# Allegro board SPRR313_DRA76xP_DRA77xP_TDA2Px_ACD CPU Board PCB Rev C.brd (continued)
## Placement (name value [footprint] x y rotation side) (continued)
DS6  LED_GRN  [LED1206-59X59]  210.06 173.99 270 top
E1  0.47uF  [EMI-NFM21P]  31.11 155.57 270 top
E2  0.47uF  [EMI-NFM21P]  74.55 73.41 270 top
E3  0.47uF  [EMI-NFM21P]  74.55 68.96 270 top
E4  0.47uF  [EMI-NFM21P]  71.5 68.96 270 top
E5  0.47uF  [EMI-NFM21P]  71.5 73.41 270 top
E6  0.47uF  [EMI-NFM21P]  68.45 68.96 270 top
E7  0.47uF  [EMI-NFM21P]  121.16 58.39 180 top
E8  0.47uF  [EMI-NFM21P]  121.16 51.44 180 top
E9  0.47uF  [EMI-NFM21P]  121.16 55.22 180 top
E10  0.47uF  [EMI-NFM21P]  116.08 47.5 180 top
E11  0.47uF  [EMI-NFM21P]  163.7 45.72 90 top
E12  0.47uF  [EMI-NFM21P]  74.42 42.77 0 top
EXP_P1  QSE-020-01-L-D-A-K  [QSE_020]  62.1 87.2 270 bottom
EXP_P2  QSE-060-01-L-D-A-K  [QSE-060-0X-X-D-A]  92.58 112.6 0 bottom
EXP_P3  QSE-020-01-L-D-A-K  [QSE_020]  123.06 87.2 270 bottom
F1  8A_QuickBlow  [FUSEFOLDER-OMNI-BLOK]  190.25 164.72 90 top
FL1  DLW21SN121HQ2  [EMI-36X15-DLW21]  73.79 165.74 90 top
FL2  DLW21SN900HQ2  [EMI-36X15-DLW21-RDPADS]  151.64 164.59 90 top
FL3  DLW21SN900HQ2  [EMI-36X15-DLW21-RDPADS]  16.76 105.79 180 top
FL4  DLW21SN900HQ2  [EMI-36X15-DLW21-RDPADS]  18.8 102.74 180 top
FL5  DLW21SN900HQ2  [EMI-36X15-DLW21-RDPADS]  18.8 98.68 180 top
FL6  DLW21SN900HQ2  [EMI-36X15-DLW21-RDPADS]  16.76 95.63 180 top
FL7  DLW21SN121HQ2  [EMI-36X15-DLW21-RDPADS]  9.14 85.47 180 top
FL8  LW21SN900HQ2  [EMI-36X15-DLW21-RDPADS]  14.35 79.88 180 top
FL9  LW21SN900HQ2  [EMI-36X15-DLW21-RDPADS]  14.35 76.71 180 top
FL10  DLW21SN121HQ2  [EMI-36X15-DLW21]  17.14 123.95 180 bottom
FL11  DLW21SN121HQ2  [EMI-36X15-DLW21]  17.14 121.67 180 bottom
J1  NP  [JUMP1X2-6040]  4.7 22.35 0 top
J2  PJ-063BH  [PWRJACK-CUI-PJ063BH]  180.21 180.21 0 top
J3  USBMINI_AB  [SAMTEC-MUSB]  166.12 172.36 180 top
J4  NO-POP(2.54MM)  [JUMP1X2-6040]  15.75 163.58 180 top
J5  NO-POP(2.54MM)  [JUMP1X2-6040]  18.29 158.5 180 top
J6  NO-POP(2.54MM)  [JUMP1X2-6040]  15.75 153.42 180 top
J7  NP  [JUMP1X2-6040]  210.06 167.89 0 top
J8  MOLEX 052559-3679 ( mirror )  [CONN36-52559-MIRROR]  58.93 149.73 0 top
J9  NP-HEADER 3  [JUMP1X3-6040]  217.68 153.92 90 top
J10  NP-HEADER 3  [JUMP1X3-6040]  2.41 137.03 90 top
J11  99S20D-40MA5-Y-HSD-2  [CONN-RA-99S20D]  6.48 122.81 90 top
J12  SATA HEADER 7  [MOLEX-67491-002]  45.97 93.85 270 top
J13  MIPI-QSH-030  [QSH-030-01-F]  151.13 37.72 180 top
J14  PM5  [JUMP1X5-6040]  217.55 36.07 180 top
J15  MOLEX 052559-3679  [CONN36-52559-MIRROR]  41.25 31.5 180 top
J16  1757242  [CONN2-MSTBA]  37.21 18.92 180 top
J17  FH12A-40S-0.5SH(55)  [FH12-40-SH]  126.87 123.57 270 bottom
J18  AXT340124  [CONN-AXT40]  215.26 54.86 270 bottom
J19  QSH-030-01  [QSH-030-01-F]  171.13 27.65 0 bottom
J20  HEADER 5X2  [JUMP2X5-6040]  206.88 12.57 90 top
J21  HEADER 5X2  [JUMP2X5-6040]  196.72 20.83 90 top
JP1  NP-(HEADER 2  [JUMP1X2-6040]  193.29 32.51 0 top
JP2  NP-(HEADER 2  [JUMP1X2-6040]  207.77 32.51 0 top
L1  220Ohm  [L805-35X60]  36.2 164.59 270 top
L2  220Ohm  [L603-35X45]  169.8 168.91 0 top
L3  220Ohm  [L805-35X60]  20.57 166.62 180 top
L4  1K  [L603-35X45]  157.99 163.19 0 top
L5  220Ohm  [L603-35X45]  145.67 162.31 90 top
L6  220Ohm  [L603-35X45]  145.16 157.35 0 top
L7  220Ohm  [L603-35X45]  22.73 154.81 270 top
L8  220Ohm  [L603-35X45]  160.4 138.56 270 top
L9  220Ohm  [L603-35X45]  162.31 138.56 270 top
L10  2.2uH ( 7443330220)  [CHOKE-POWER-WE-HCC]  163.19 121.92 270 top
L11  8.2uH(744771008 )  [IND2-115X213-12MM]  188.59 120.65 270 top
L12  1uH  [IND2-65X90-IHLP1616]  163.07 79.38 270 top
L13  1uH  [IND2-65X90-IHLP1616]  154.18 72.52 0 top
L14  1uH  [IND2-65X90-IHLP1616]  173.1 72.77 180 top
L15  0.47uH  [IND2520-40X80]  136.02 65.28 270 top
L16  0.47uH  [IND2520-40X80]  139.19 65.28 270 top
L17  1uH  [IND2-65X90-IHLP1616]  154.18 67.69 0 top
L18  1uH  [IND2-65X90-IHLP1616]  166.24 60.45 90 top
L19  220Ohm  [L603-35X45]  50.8 51.31 0 top
L20  0.47uH  [IND2520-40X80]  135.89 54.86 90 top
L21  0.47uH  [IND2520-40X80]  139.19 54.86 90 top
L22  220Ohm  [L805-35X60]  170.18 50.42 270 top
L23  220Ohm  [L805-35X60]  185.42 38.23 270 top
L24  220Ohm  [L805-35X60]  181.99 35.69 270 top
L25  220Ohm  [L603-35X45]  28.32 130.81 90 bottom
L26  220Ohm  [L603-35X45]  20.19 127.38 180 bottom
L27  220Ohm  [L603-35X45]  36.58 124.46 0 bottom
L28  220Ohm  [L603-35X45]  36.58 122.68 0 bottom
L29  220Ohm  [L603-35X45]  36.58 121.03 0 bottom
L30  NP  [L805-35X60]  15.11 12.7 0 top
L31  0.47uH  [IND2520-40X80]  145.16 18.92 90 bottom
L32  220Ohm  [L603-35X45]  52.45 111.51 270 top
L33  220Ohm  [L603-35X45]  45.72 114.05 270 top
MHC1  MHC1  [MH62]  46.93 158.62 0 top
MHC2  MHC2  [MH62]  70.93 158.62 0 top
MHC3  MHC2  [MH93-125]  53.19 22.58 0 bottom
MHC4  MHC1  [MH93-125]  29.21 22.58 0 bottom
NOREF  -  []  220.85 0 90 top
NOREF#2  -  [unnamed#2]  5.08 185.29 0 top
NOREF#3  -  []  220.85 0 90 top
NOREF#4  -  [unnamed#2]  58.47 175.13 0 top
NOREF#5  -  []  -191.39 -215.57 0 top
NOREF#6  -  []  220.85 10.16 90 top
NOREF#7  -  [unnamed#2]  215.77 5.08 0 top
NOREF#8  -  [unnamed#2]  5.08 5.08 0 top
NOREF#9  -  []  0 190.37 0 top
NOREF#10  -  []  -191.39 -215.57 0 top
NOREF#11  -  [unnamed#2]  215.77 185.29 0 top
NOREF#12  -  []  65.02 120.9 0 top
NOREF#13  -  [unnamed#3]  156.72 30.99 0 bottom
NOREF#14  -  [unnamed#2]  5.08 5.08 180 bottom
NOREF#15  -  [unnamed#2]  5.08 185.29 180 bottom
NOREF#16  -  [unnamed#3]  187.2 30.99 0 bottom
NOREF#17  -  [unnamed#2]  215.77 5.08 180 bottom
NOREF#18  -  [unnamed#3]  202.44 13.84 0 bottom
NOREF#19  -  [unnamed#3]  208.15 60.83 0 bottom
NOREF#20  -  [unnamed#2]  215.77 185.29 180 bottom
P1  D4S20G-400A5-C  [CON_MB261]  150.37 174.96 0 top
P2  USB-A connector  [USB_A_SH]  77.34 169.42 180 top
P3  6605814-6  [AMP-6605814]  100.84 166.12 180 top
P4  6605814-6  [AMP-6605814]  121.92 166.12 180 top
P5  QSH-020-01-L-D-DP-A  [QSH-020-DP-A]  6.22 163.7 90 top
P6  PCIe 4X Connector  [PCIE_SMT_64]  34.38 139.19 90 top
P7  HDMI-RA-19-TYPEA  [HDMI-SMT-W-FLANGE-RDPADS]  8.5 102.74 270 top
P8  AU-Y1009_3-AB-R  [USB-AB-F-10PTH-RDPADS]  4.86 81.79 270 top
P9  MEC6-150-02-S-D-RA1  [MEC6-150-RA1]  7.49 52.58 180 top
P10  Mic In  [ST_3500]  156.08 17.53 180 top
P11  Line In  [ST_3500]  166.88 17.53 180 top
P12  Line Out  [ST_3500]  177.67 17.53 180 top
P13  Headphone Out  [ST_3500]  188.47 17.53 180 top
P14  Micro SD, Reverse  [MOLEX-502774-0891]  135.69 169.88 0 bottom
P15  QSH-020-01-L-D-DP-A  [QSH-020-DP-A#2]  41.05 32.28 180 bottom
Q1  SUD50P04-08  [TO-252-D-PAK]  192.79 146.81 180 top
Q2  CSD18501Q5A  [PWR-Q5A-SLPS319]  183.51 157.23 180 top
Q3  BSS138  [SOT23-28X44-GSD]  4.06 149.35 90 top
Q4  BSS138  [SOT23-28X44-GSD]  198.5 158.37 180 top
Q5  BSS138  [SOT23-28X44-GSD]  208.91 155.07 180 top
Q6  BSS138  [SOT23-28X44-GSD]  203.58 156.59 0 top
Q7  CSD18501Q5A  [PWR-Q5A-SLPS319]  168.91 133.35 0 top
Q8  CSD18501Q5A  [PWR-Q5A-SLPS319]  181.61 133.35 0 top
Q9  CSD18501Q5A  [PWR-Q5A-SLPS319]  171.45 129.79 180 top
Q10  CSD18501Q5A  [PWR-Q5A-SLPS319]  179.07 129.79 180 top
Q11  BSS138  [SOT23-28X44-GSD]  48.13 168.53 0 bottom
Q12  BSS138  [SOT23-28X44-GSD]  43.05 168.53 0 bottom
Q13  BSS138  [SOT23-28X44-GSD]  207.65 45.59 0 bottom
Q16  NX3008CBKS  [SOT363-16X45]  157.86 60.2 90 top
Q18  BSS138PS  [SOT363-16X45]  199.14 132.08 0 top
Q19  BSS138PS  [SOT363-16X45]  191.39 63.63 180 top
R1  100K  [R402-25]  36.2 161.42 270 top
R2  1K  [R402-25]  136.65 172.72 270 top
R3  10.7K  [R603-35X45]  84.96 169.42 180 top
R7  10K  [R402-25]  171.7 167.39 180 top
R8  100K  [R402-25]  18.03 166.62 270 top
R9  10K  [R402-25]  136.02 166.5 270 top
R10  NP  [R201-6P6SPC]  13.08 165.48 0 top
R11  NP  [R201-6P6SPC]  13.08 164.21 0 top
R12  10K  [R402-25]  52.7 163.96 270 top
R13  1K  [R402-25]  63.5 161.29 180 top
R14  NP  [R201-6P6SPC]  13.08 160.4 0 top
R15  4.99K  [R603-35X45]  82.3 160.15 180 top
R16  10K  [R402-25]  63.5 160.02 180 top
R17  NP  [R201-6P6SPC]  13.08 159.13 0 top
R18  1K  [R402-25]  63.5 157.48 180 top
R19  1.5K  [R402-25]  63.5 156.21 180 top
R20  10.7K  [R603-35X45]  78.49 156.21 90 top
R21  61.9K  [R603-35X45]  204.34 170.05 180 top
R22  NP  [R201-6P6SPC]  13.08 155.32 0 top
R23  4.7K  [R402-25]  192.79 156.08 0 top
R24  0  [R201-6P6SPC]  102.11 154.18 0 top
R25  NP  [R201-6P6SPC]  13.08 154.05 0 top
R26  NP  [R402-25]  24.64 154.05 90 top
R27  10K  [R402-25]  25.65 154.05 270 top
R28  10K  [R402-25]  26.67 154.05 270 top
R29  0  [R402-25]  27.69 154.05 90 top
R30  10K  [R402-25]  145.03 153.92 0 top
R31  61.9K  [R603-35X45]  204.34 165.74 180 top
R32  0.01  [R0508]  187.07 143.51 180 top
R33  2K  [R402-25]  97.66 151 0 top
R34  0  [R402-25]  119.38 150.24 270 top
R35  10K  [R402-25]  120.4 150.24 90 top
R36  1.5K  [R402-25]  198.5 154.81 270 top
R37  NP  [R402-25]  83.06 149.22 180 top
R38  NP  [R402-25]  86.23 149.22 0 top
R39  84.5K  [R603-35X45]  204.34 167.89 0 top
R40  NP  [R402-25]  83.06 148.21 180 top
R41  NP  [R402-25]  86.23 148.21 180 top
R42  10K  [R402-25]  146.3 147.96 0 top
R43  NP  [R402-25]  83.06 147.19 180 top
R44  NP  [R402-25]  86.23 147.19 180 top
R45  10K  [R402-25]  2.54 147.07 0 top
R46  1K  [R402-25]  203.07 159.13 0 top
R47  10K  [R402-25]  212.47 155.96 90 top
R48  0  [R402-25]  19.56 145.92 0 top
R49  NP  [R402-25]  87.5 145.92 90 top
R50  4.7K  [R402-25]  2.54 145.8 180 top
R51  10K  [R402-25]  4.95 145.8 0 top
R52  10K  [R402-25]  118.11 145.67 180 top
R53  4.99K  [R603-35X45]  79.25 143.76 270 top
R54  22  [R402-25]  54.1 145.54 90 top
R55  22  [R402-25]  55.12 145.54 90 top
R56  22  [R402-25]  63.5 145.29 90 top
R57  100  [R402-25]  37.21 145.16 180 top
R58  10K  [R402-25]  14.99 144.53 180 top
R59  820  [R402-25]  155.45 144.4 180 top
R60  10K  [R402-25]  211.2 153.54 90 top
R61  4.7K  [R402-25]  212.47 153.54 270 top
R62  4.7K  [R402-25]  14.99 143.38 180 top
R63  1K  [R402-25]  155.45 143.26 0 top
R64  NP  [R402-25]  87.5 142.75 90 top
R65  1.87K  [R603-35X45]  15.24 141.99 180 top
R66  10K  [R201-6P6SPC]  202.95 154.05 0 top
R67  4.7K  [R402-25]  159 141.22 180 top
R68  4.7K  [R402-25]  14.99 140.59 180 top
R69  NP  [R402-25]  106.81 135 180 top
R70  1K  [R201-6P6SPC]  117.98 135 270 top
R71  1K  [R201-6P6SPC]  119.25 135 270 top
R72  1K  [R201-6P6SPC]  120.52 135 270 top
R73  1K  [R201-6P6SPC]  121.79 135 270 top
R74  1K  [R201-6P6SPC]  123.06 135 270 top
R75  1K  [R201-6P6SPC]  124.33 135 270 top
R76  1K  [R201-6P6SPC]  125.6 135 270 top
R77  1K  [R201-6P6SPC]  126.87 135 270 top
R78  1K  [R201-6P6SPC]  130.18 135 270 top
R79  1K  [R201-6P6SPC]  131.44 135 270 top
R80  1K  [R201-6P6SPC]  132.72 135 270 top
R81  1K  [R201-6P6SPC]  133.99 135 270 top
R82  1K  [R201-6P6SPC]  135.25 135 270 top
R83  1K  [R201-6P6SPC]  136.53 135 270 top
R84  1K  [R201-6P6SPC]  137.79 135 270 top
R85  1K  [R201-6P6SPC]  139.06 135 270 top
R86  1.5K  [R402-25]  106.81 133.86 180 top
R87  10  [R603-35X45]  162.56 133.35 0 top
R88  10  [R603-35X45]  189.87 133.35 180 top
R89  0  [R402-25]  40.26 132.08 90 top
R90  0  [R402-25]  41.27 132.08 90 top
R91  0  [R201-6P6SPC]  106.68 131.95 270 bottom
R92  47K  [R402-25]  33.02 132.08 0 top
R93  0  [R402-25]  45.21 132.08 90 top
R94  0  [R402-25]  46.23 132.08 90 top
R95  4.7K  [R402-25]  211.71 141.1 90 top
R96  4.7K  [R402-25]  214.5 141.1 90 top
R97  10K  [R402-25]  215.77 141.1 90 top
R98  1.87K  [R603-35X45]  213.11 140.84 90 top
R99  49.9  [R402-25]  33.02 131.06 0 top
R100  2K  [R402-25]  104.01 130.68 0 top
R101  1K  [R402-25]  29.08 130.56 90 top
R102  47K  [R402-25]  33.02 130.05 0 top
R103  NP  [R402-25]  89.41 129.41 180 top
R104  NP  [R402-25]  92.58 128.91 0 top
R105  NP  [R402-25]  89.41 128.4 180 top
R106  NP  [R402-25]  92.58 127.89 180 top
R107  100  [R402-25]  62.87 132.08 180 top
R108  NP  [R402-25]  89.41 127.38 180 top
R109  NP  [R402-25]  92.58 126.87 180 top
R110  10K  [R402-25]  23.88 126.75 0 top
R111  49.9  [R402-25]  23.88 125.73 0 top
R112  NP  [R402-25]  93.85 125.6 90 top
R113  10K  [R201-6P6SPC]  117.98 123.55 270 top
R114  10K  [R201-6P6SPC]  119.25 123.55 270 top
R115  10K  [R201-6P6SPC]  120.52 123.55 270 top
R116  10K  [R201-6P6SPC]  121.79 123.55 270 top
R117  10K  [R201-6P6SPC]  123.06 123.55 270 top
R118  10K  [R201-6P6SPC]  124.33 123.55 270 top
R119  10K  [R201-6P6SPC]  125.6 123.55 270 top
R120  10K  [R201-6P6SPC]  126.87 123.55 270 top
R121  10K  [R201-6P6SPC]  130.18 123.55 270 top
R122  10K  [R201-6P6SPC]  131.44 123.55 270 top
R123  10K  [R201-6P6SPC]  132.72 123.55 270 top
R124  10K  [R201-6P6SPC]  133.99 123.55 270 top
R125  10K  [R201-6P6SPC]  135.25 123.55 270 top
R126  10K  [R201-6P6SPC]  136.53 123.55 270 top
R127  10K  [R201-6P6SPC]  137.79 123.55 270 top
R128  10K  [R201-6P6SPC]  139.06 123.55 270 top
R129  NP  [R402-25]  93.85 122.43 90 top
R130  10K  [R402-25]  103.12 117.22 270 top
R131  0  [R402-25]  101.47 116.71 180 top
R132  4.7K  [R402-25]  23.75 116.08 90 top
R133  0  [R402-25]  116.08 114.68 0 top
R134  10K  [R201-6P6SPC]  210.44 83.31 180 bottom
R135  0  [R402-25]  115.44 112.52 90 top
R136  10K  [R402-25]  116.46 112.52 270 top
R137  10K  [R201-6P6SPC]  210.44 82.04 180 bottom
R138  0.005  [R2725-125X250]  164.85 111.12 90 top
R139  10K  [R201-6P6SPC]  210.44 79.5 180 bottom
R140  4.99K  [R603-35X45]  31.5 106.43 0 top
R141  0.015  [R2512]  184.15 108.84 90 top
R142  10.7K  [R603-35X45]  31.24 96.14 0 top
R143  0  [R201-6P6SPC]  132.08 107.82 0 top
R144  0  [R402-25]  101.47 107.7 0 top
R145  10  [R402-25]  99.31 105.41 180 top
R146  10  [R402-25]  101.47 105.41 180 top
R147  10K  [R201-6P6SPC]  210.44 74.42 180 bottom
R148  49.9K  [R603-35X45]  163.96 104.14 180 top
R149  16K  [R402-25]  167.51 104.14 180 top
R150  0  [R402-25]  172.34 104.14 90 top
R151  0  [R402-25]  111.76 104.01 0 top
R152  10K  [R402-25]  113.41 103.76 90 top
R153  10K  [R201-6P6SPC]  210.44 73.15 180 bottom
R154  49.9  [R402-25]  163.7 102.23 0 top
R155  16K  [R402-25]  178.31 102.23 0 top
R156  84.5K  [R603-35X45]  181.86 102.23 0 top
R157  NP  [R201-6P6SPC]  110.36 49.28 180 bottom
R158  NP  [R201-6P6SPC]  110.36 48.39 180 bottom
R159  49.9  [R402-25]  181.86 100.33 180 top
R160  0.01  [R0508]  164.34 98.3 270 top
R161  10K  [R201-6P6SPC]  161.8 95.25 0 top
R162  0.01  [R0508]  182.12 93.85 90 top
R163  2.2K  [R402-25]  161.8 94.36 0 top
R164  0  [R201-6P6SPC]  98.17 91.69 90 top
R165  100  [R402-25]  78.05 78.36 180 top
R166  100  [R402-25]  81.61 78.36 180 top
R167  100  [R402-25]  79.83 77.47 180 top
R168  2.2K  [R402-25]  161.93 92.33 0 top
R169  NP  [R402-25]  86.49 88.9 270 top
R170  0  [R402-25]  87.76 88.9 270 top
R171  0  [R402-25]  96.27 88.39 270 top
R172  NP  [R402-25]  91.44 88.39 270 top
R173  0  [R402-25]  92.71 88.39 270 top
R174  NP  [R402-25]  97.66 88.52 270 top
R175  0  [R402-25]  98.93 88.52 270 top
R176  0  [R201-6P6SPC]  100.71 77.98 270 top
R177  0  [R201-6P6SPC]  102.49 77.98 270 top
R178  0  [R201-6P6SPC]  101.6 77.98 270 top
R179  0.01  [R0508]  163.83 83.95 0 top
R180  NP  [R402-25]  89.15 88.39 270 top
R181  0  [R402-25]  90.3 88.39 270 top
R182  0.01  [R0508]  159.26 84.33 0 top
R183  0.01  [R0508]  153.92 84.33 0 top
R184  NP  [R402-25]  93.85 88.39 270 top
R185  0  [R402-25]  95.12 88.39 270 top
R186  NP  [R402-25]  95.76 85.22 270 top
R187  0  [R402-25]  97.03 85.22 270 top
R188  NP  [R201-6P6SPC]  118.49 150.24 90 top
R189  0.01  [R0508]  176.91 81.79 0 top
R190  NP  [R402-25]  69.72 77.09 180 bottom
R191  0.01  [R0508]  137.54 71.12 0 top
R192  0.01  [R0508]  177.93 65.53 270 top
R193  0  [R201-6P6SPC]  13.59 70.99 90 top
R194  0.02  [R603-35X45]  180.72 73.79 0 top
R195  22  [R201-6P6SPC]  113.41 66.29 180 top
R196  0.01  [R0508]  177.93 69.22 270 top
R197  22  [R201-6P6SPC]  118.24 66.17 180 top
R198  22  [R201-6P6SPC]  118.24 60.2 180 top
R199  22  [R201-6P6SPC]  118.24 68.07 180 top
R200  22  [R201-6P6SPC]  118.24 68.96 180 top
R201  22  [R201-6P6SPC]  118.24 65.28 180 top
R202  22  [R201-6P6SPC]  118.24 67.18 180 top
R203  22  [R201-6P6SPC]  113.41 67.31 180 top
R204  0.01  [R0508]  176.66 61.85 270 top
R205  0.02  [R603-35X45]  144.65 63.75 0 top
R206  0  [R201-6P6SPC]  122.56 63.75 180 top
R207  22  [R201-6P6SPC]  113.41 64.39 180 top
R208  0.01  [R0508]  149.1 67.18 90 top
R209  0  [R201-6P6SPC]  124.84 58.8 180 top
R210  22  [R201-6P6SPC]  118.24 61.98 180 top
R211  100  [R402-25]  74.8 58.04 270 bottom
R212  22  [R201-6P6SPC]  113.41 65.28 180 top
R213  0  [R201-6P6SPC]  118.24 59.18 180 top
R214  0  [R201-6P6SPC]  124.84 59.31 0 bottom
R215  28K  [R402-25]  133.1 60.83 180 top
R216  0  [R201-6P6SPC]  124.84 56.26 180 top
R217  NP  [R402-25]  21.08 58.55 90 top
R218  0  [R201-6P6SPC]  124.84 57.91 180 top
R219  0.01  [R0508]  162.69 56.01 180 top
R220  0.01  [R0508]  182.12 54.48 270 top
R221  0  [R201-6P6SPC]  124.84 54.86 180 top
R222  10K  [R402-25]  19.56 56.26 270 top
R223  10  [R201-6P6SPC]  155.45 54.86 180 top
R224  0  [R201-6P6SPC]  124.84 57.02 0 top
R225  0.02  [R603-35X45]  144.91 56.64 0 top
R226  10  [R201-6P6SPC]  119.25 73.28 0 top
R227  2.2K  [R402-25]  158.37 54.48 180 top
R228  0  [R201-6P6SPC]  124.84 53.09 0 top
R229  10  [R201-6P6SPC]  155.45 53.34 180 top
R230  10  [R201-6P6SPC]  119.25 72.26 0 top
R231  0  [R201-6P6SPC]  124.84 54.1 180 top
R232  2.2K  [R402-25]  158.37 52.58 180 top
R233  0  [R201-6P6SPC]  67.69 56.77 180 bottom
R234  0  [R201-6P6SPC]  64.52 53.72 180 bottom
R235  0  [R201-6P6SPC]  117.6 45.09 180 top
R236  NP  [R402-25]  175.77 49.66 270 top
R237  10  [R402-25]  177.04 49.66 270 top
R238  10  [R402-25]  178.31 49.66 270 top
R239  10  [R402-25]  179.58 49.66 270 top
R240  10  [R402-25]  180.85 49.66 270 top
R241  22  [R402-25]  182.12 49.66 270 top
R242  10K  [R201-6P6SPC]  41.91 42.42 180 top
R243  0  [R201-6P6SPC]  61.09 49.02 180 bottom
R244  0  [R201-6P6SPC]  20.19 48.9 90 top
R245  0  [R201-6P6SPC]  112.39 45.59 180 top
R246  NP  [R402-25]  166.75 48.26 180 top
R247  0  [R201-6P6SPC]  62.23 47.75 180 bottom
R248  10K  [R201-6P6SPC]  158.62 48.26 0 top
R249  0.01  [R0508]  137.54 49.02 180 top
R250  10K  [R201-6P6SPC]  155.07 57.28 0 top
R251  2K  [R402-25]  166.75 47.12 180 top
R252  0  [R201-6P6SPC]  112.52 43.43 0 top
R253  NP  [R201-6P6SPC]  41.91 40.89 180 top
R254  NP  [R402-25]  166.75 45.97 180 top
R255  0  [R201-6P6SPC]  117.6 44.07 180 top
R256  NP  [R402-25]  166.75 44.83 180 top
R257  NP  [R201-6P6SPC]  41.91 44.32 0 top
R259  10K  [R201-6P6SPC]  41.91 43.31 180 top
R263  10K  [R201-6P6SPC]  195.07 40.89 0 top
R264  10K  [R201-6P6SPC]  206.5 40.26 180 top
R265  22  [R201-6P6SPC]  118.62 41.53 270 top
R266  NP  [R201-6P6SPC]  121.16 49.78 0 top
R267  2K  [R402-25]  121.16 46.35 0 top
R268  0  [R201-6P6SPC]  195.07 38.86 180 top
R269  10K  [R201-6P6SPC]  121.16 49.02 180 top
R270  0  [R201-6P6SPC]  206.76 38.35 0 top
R271  0  [R201-6P6SPC]  195.07 36.96 180 top
R272  22  [R201-6P6SPC]  119.13 38.23 180 top
R273  0  [R402-25]  13.84 34.92 90 top
R274  17.4K  [R603-35X45]  2.54 32.13 0 top
R275  100  [R402-25]  183.51 30.61 270 top
R276  36  [R402-25]  137.92 27.3 0 top
R277  NP-1K  [R402-25]  141.99 28.7 180 top
R278  36  [R402-25]  137.92 26.29 0 top
R279  20K  [R402-25]  184.02 25.91 0 top
R280  NP-1K  [R402-25]  141.99 27.56 180 top
R281  10K  [R402-25]  141.99 30.99 0 top
R282  0  [R402-25]  141.99 29.84 0 top
R283  100K  [R402-25]  152.91 27.18 0 bottom
R284  NP-10K  [R402-25]  138.81 29.46 180 top
R285  0  [R402-25]  138.81 30.61 0 top
R286  28K  [R402-25]  152.91 24.13 0 bottom
R287  62  [R1206-40X70]  201.17 18.29 180 bottom
R288  62  [R1206-40X70]  201.17 25.91 0 bottom
R289  62  [R1206-40X70]  211.2 19.3 180 top
R290  62  [R1206-40X70]  216.28 19.3 180 top
R291  28K  [R402-25]  152.91 22.1 0 bottom
R292  0  [R402-25]  60.07 15.75 180 top
R296  NP  [R402-25]  60.07 14.73 180 top
R297  1K  [R402-25]  213.74 172.72 90 bottom
R298  10K  [R402-25]  16.76 176.78 90 bottom
R299  220  [R402-25]  121.79 175.77 180 bottom
R300  220  [R402-25]  113.54 175.77 0 bottom
R301  220  [R402-25]  100.84 175.77 180 bottom
R302  220  [R402-25]  91.95 175.77 0 bottom
R305  NP  [R402-25]  70.99 177.16 0 bottom
R306  10K  [R402-25]  70.99 176.02 180 bottom
R307  0  [R402-25]  44.2 174.37 180 bottom
R308  10K  [R402-25]  36.58 174.37 0 bottom
R309  10K  [R402-25]  27.3 160.91 180 bottom
R310  NP  [R402-25]  76.2 176.15 180 bottom
R311  10K  [R402-25]  76.2 175.01 0 bottom
R312  680K  [R402-25]  47.62 172.47 180 bottom
R313  680K  [R402-25]  42.55 172.47 180 bottom
R314  330K  [R402-25]  47.62 171.32 0 bottom
R315  330K  [R402-25]  42.55 171.32 0 bottom
R316  0  [R201-6P6SPC]  8.51 165.48 180 bottom
R317  10K  [R402-25]  56.01 163.7 90 bottom
R318  10K  [R402-25]  149.48 162.81 270 bottom
R319  10K  [R402-25]  59.18 162.56 90 bottom
R320  47K  [R402-25]  47.62 165.99 0 bottom
R321  47K  [R402-25]  42.55 165.99 0 bottom
R322  0  [R402-25]  4.06 161.93 90 bottom
R323  NP  [R402-25]  126.11 160.66 180 bottom
R324  1.87K  [R603-35X45]  82.3 160.27 0 bottom
R325  NP  [R402-25]  147.07 160.02 0 bottom
R326  40.2K  [R402-25]  147.07 158.88 180 bottom
R327  11K  [R402-25]  99.57 157.48 90 bottom
R328  10K  [R402-25]  56.01 157.35 270 bottom
R329  NP  [R201-6P6SPC]  168.78 157.23 90 bottom
R330  47K  [R402-25]  140.84 156.72 90 bottom
R331  47K  [R402-25]  137.29 156.72 270 bottom
R332  NP  [R402-25]  136.27 156.72 90 bottom
R333  47K  [R402-25]  132.72 156.72 270 bottom
R334  47K  [R402-25]  131.7 156.72 90 bottom
R335  47K  [R402-25]  128.14 156.72 270 bottom
R336  NP  [R402-25]  155.19 156.21 0 bottom
R337  40.2K  [R402-25]  155.19 155.07 180 bottom
R338  NP  [R402-25]  99.57 154.69 270 bottom
R339  33  [R402-25]  128.91 154.05 0 bottom
R340  NP  [R402-25]  27.69 154.05 90 bottom
R341  1K  [R402-25]  121.28 153.67 90 bottom
R342  0  [R603-35X45]  119.25 153.67 90 bottom
R343  33  [R402-25]  139.57 153.54 90 bottom
R344  33  [R402-25]  138.56 153.54 90 bottom
R345  33  [R402-25]  135 153.54 90 bottom
R346  33  [R402-25]  133.99 153.54 90 bottom
R347  33  [R402-25]  130.43 153.54 90 bottom
R348  2K  [R402-25]  83.06 153.54 0 bottom
R349  10K  [R402-25]  26.67 153.03 90 bottom
R350  1K  [R402-25]  199.52 176.91 90 bottom
R351  NP  [R402-25]  83.06 152.15 180 bottom
R352  22  [R402-25]  55.63 151.13 90 bottom
R353  NP  [R402-25]  83.06 151.13 180 bottom
R354  10K  [R402-25]  66.67 151.13 270 bottom
R355  22  [R402-25]  63.63 151.13 90 bottom
R356  5.6K  [R402-25]  83.06 149.1 180 bottom
R357  2.49K  [R402-25]  83.06 148.08 180 bottom
R358  10K  [R402-25]  146.3 147.96 0 bottom
R359  10K  [R201-6P6SPC]  117.6 146.43 0 bottom
R360  10K  [R201-6P6SPC]  117.6 145.67 0 bottom
R361  10.7K  [R603-35X45]  77.47 145.54 0 bottom
R362  10K  [R402-25]  114.55 145.16 0 bottom
R363  NP  [R402-25]  117.09 144.65 180 bottom
R364  10K  [R402-25]  114.55 144.15 0 bottom
R365  10K  [R402-25]  62.61 144.02 270 bottom
R366  10K  [R201-6P6SPC]  117.35 143.64 0 bottom
R367  5.6K  [R402-25]  91.11 143.18 180 bottom
R368  NP  [R402-25]  88.82 143.18 180 bottom
R369  10K  [R402-25]  29.72 142.88 90 bottom
R370  10K  [R402-25]  27.81 142.88 90 bottom
R371  10K  [R402-25]  117.09 142.62 180 bottom
R372  10K  [R402-25]  26.29 142.11 180 bottom
R373  2.49K  [R402-25]  91.11 142.03 0 bottom
R374  NP  [R402-25]  88.82 142.03 0 bottom
R375  10K  [R201-6P6SPC]  117.6 141.6 0 bottom
R376  10K  [R201-6P6SPC]  117.6 140.84 0 bottom
R377  10K  [R402-25]  149.22 140.46 180 bottom
R378  NP  [R402-25]  146.05 139.7 0 bottom
R379  11K  [R402-25]  104.01 139.45 180 bottom
R380  10K  [R201-6P6SPC]  117.86 139.19 0 bottom
R381  NP  [R402-25]  38.35 137.54 0 bottom
R382  10K  [R201-6P6SPC]  146.05 138.56 180 bottom
R383  10K  [R201-6P6SPC]  117.86 138.43 0 bottom
R384  47K  [R402-25]  152.78 138.18 270 bottom
R385  47K  [R402-25]  151.76 138.18 270 bottom
R386  47K  [R402-25]  150.75 138.18 270 bottom
R387  47K  [R402-25]  149.73 138.18 270 bottom
R388  47K  [R402-25]  148.72 138.18 270 bottom
R389  47K  [R402-25]  147.7 138.18 270 bottom
R390  10K  [R201-6P6SPC]  117.86 137.67 0 bottom
R391  10K  [R201-6P6SPC]  146.05 137.54 180 bottom
R392  10K  [R201-6P6SPC]  117.86 136.91 0 bottom
R393  10K  [R201-6P6SPC]  146.05 136.53 180 bottom
R394  220  [R402-25]  82.04 135.89 180 bottom
R395  47K  [R402-25]  144.78 135.51 0 bottom
R396  10K  [R201-6P6SPC]  120.4 135.51 90 bottom
R397  10K  [R201-6P6SPC]  117.86 135.51 90 bottom
R398  47K  [R402-25]  144.78 134.37 0 bottom
R399  NP  [R402-25]  106.43 134.37 270 bottom
R400  NP  [R402-25]  75.56 133.22 0 bottom
R401  0  [R402-25]  184.02 133.1 0 bottom
R402  0  [R402-25]  169.29 133.1 180 bottom
R403  2K  [R402-25]  89.41 133.1 0 bottom
R404  10K  [R402-25]  30.23 133.1 180 bottom
R405  NP  [R402-25]  79.63 132.59 0 bottom
R406  10  [R201-6P6SPC]  32.89 132.08 180 bottom
R407  NP  [R402-25]  89.41 131.95 180 bottom
R408  10K  [R402-25]  79.25 131.19 180 bottom
R409  NP  [R402-25]  89.41 130.94 180 bottom
R410  40.2K  [R402-25]  20.19 130.68 0 bottom
R411  10K  [R402-25]  67.06 130.18 180 bottom
R412  NP  [R402-25]  79.38 130.05 0 bottom
R413  10  [R201-6P6SPC]  32.89 130.05 180 bottom
R414  0  [R402-25]  177.55 129.79 0 bottom
R415  47K  [R402-25]  148.21 129.67 90 bottom
R416  47K  [R402-25]  147.07 129.67 270 bottom
R417  0  [R402-25]  169.54 129.29 270 bottom
R418  0  [R402-25]  150.62 129.29 90 bottom
R419  10K  [R402-25]  79.25 128.91 180 bottom
R420  NP  [R402-25]  152.27 128.78 180 bottom
R421  5.6K  [R402-25]  89.41 128.78 180 bottom
R422  NP  [R402-25]  67.06 128.91 0 bottom
R423  NP  [R402-25]  20.19 128.65 180 bottom
R424  2.49K  [R402-25]  89.41 127.76 180 bottom
R425  10K  [R402-25]  60.33 126.62 90 bottom
R426  10K  [R402-25]  59.69 131.57 0 bottom
R427  10K  [R402-25]  62.61 125.09 180 bottom
R428  10K  [R402-25]  62.48 129.54 180 bottom
R429  10K  [R402-25]  208.41 133.73 90 bottom
R430  2K  [R402-25]  97.33 122.73 180 bottom
R431  NP  [R402-25]  95.05 122.73 180 bottom
R432  NP  [R402-25]  97.33 121.71 0 bottom
R433  NP  [R402-25]  95.05 121.71 0 bottom
R434  0  [R201-6P6SPC]  131.83 121.28 270 bottom
R435  1K  [R201-6P6SPC]  123.7 121.16 270 bottom
R436  1K  [R201-6P6SPC]  123.06 121.16 270 bottom
R437  1K  [R201-6P6SPC]  122.43 121.16 270 bottom
R438  1K  [R201-6P6SPC]  121.79 121.16 270 bottom
R439  1K  [R201-6P6SPC]  121.16 121.16 270 bottom
R440  1K  [R201-6P6SPC]  120.52 121.16 270 bottom
R441  1.5K  [R402-25]  172.09 120.78 0 bottom
R442  40.2K  [R402-25]  17.02 119.89 180 bottom
R443  1K  [R201-6P6SPC]  214 128.91 270 bottom
R444  1K  [R201-6P6SPC]  216.79 128.52 0 bottom
R445  NP  [R402-25]  177.8 118.11 90 bottom
R446  0  [R402-25]  176.66 118.11 270 bottom
R447  NP  [R402-25]  17.02 117.86 0 bottom
R448  NP  [R402-25]  20.19 116.84 180 bottom
R449  10  [R201-6P6SPC]  25.53 116.2 90 bottom
R450  10  [R201-6P6SPC]  24.77 116.2 90 bottom
R451  4.7K  [R402-25]  26.42 116.08 270 bottom
R452  10K  [R201-6P6SPC]  146.81 115.7 0 bottom
R453  10K  [R402-25]  29.84 115.57 270 bottom
R454  27K  [R402-25]  32 115.44 270 bottom
R455  1K  [R201-6P6SPC]  218.06 84.58 0 bottom
R456  40.2K  [R402-25]  20.19 114.81 0 bottom
R457  0  [R201-6P6SPC]  125.35 115.44 0 bottom
R458  NP  [R201-6P6SPC]  125.35 114.68 0 bottom
R459  1K  [R201-6P6SPC]  218.06 83.31 0 bottom
R460  10K  [R201-6P6SPC]  128.52 113.54 0 bottom
R461  NP  [R402-25]  197.49 82.42 180 bottom
R462  1K  [R201-6P6SPC]  218.06 82.04 0 bottom
R463  10K  [R402-25]  197.49 81.15 0 bottom
R464  1K  [R201-6P6SPC]  218.06 80.77 0 bottom
R465  0  [R201-6P6SPC]  129.54 111.25 0 bottom
R466  1K  [R402-25]  13.08 110.74 270 bottom
R467  NP  [R402-25]  10.16 110.74 180 bottom
R468  10K  [R402-25]  197.49 79.88 0 bottom
R469  1K  [R201-6P6SPC]  218.06 79.5 0 bottom
R470  1K  [R402-25]  17.37 109.75 90 bottom
R471  NP  [R402-25]  203.33 79.25 180 bottom
R472  NP  [R402-25]  10.16 109.73 180 bottom
R473  1.87K  [R603-35X45]  31.5 106.3 180 bottom
R474  10K  [R201-6P6SPC]  210.44 78.23 180 bottom
R475  NP  [R402-25]  197.49 78.61 180 bottom
R476  20K  [R402-25]  184.15 108.84 180 bottom
R477  1K  [R201-6P6SPC]  218.06 78.23 0 bottom
R478  10K  [R402-25]  203.33 77.98 0 bottom
R479  0  [R402-25]  179.07 108.33 0 bottom
R480  15K  [R402-25]  168.15 107.95 90 bottom
R481  1K  [R201-6P6SPC]  218.06 76.96 0 bottom
R482  10K  [R201-6P6SPC]  210.44 76.96 180 bottom
R483  NP  [R201-6P6SPC]  8.13 106.93 180 bottom
R484  NP  [R201-6P6SPC]  5.84 106.93 180 bottom
R485  1K  [R201-6P6SPC]  218.06 75.69 0 bottom
R486  100  [R402-25]  203.45 75.06 0 bottom
R487  NP  [R201-6P6SPC]  8.89 105.54 180 bottom
R488  10K  [R402-25]  168.53 63.5 90 bottom
R489  10K  [R201-6P6SPC]  76.07 105.16 0 bottom
R490  1K  [R201-6P6SPC]  218.06 74.42 0 bottom
R491  NP  [R201-6P6SPC]  8.89 104.78 180 bottom
R492  NP  [R402-25]  172.21 104.14 270 bottom
R493  10K  [R201-6P6SPC]  68.45 104.01 0 bottom
R494  NP  [R201-6P6SPC]  8.89 104.01 180 bottom
R495  1K  [R201-6P6SPC]  218.06 73.15 0 bottom
R496  10K  [R402-25]  141.99 59.44 180 bottom
R497  0  [R402-25]  197.49 83.57 180 bottom
R498  0  [R402-25]  200.66 70.87 180 bottom
R499  NP  [R402-25]  197.74 70.87 180 bottom
R500  0  [R603-35X45]  150.88 101.09 180 bottom
R501  10K  [R201-6P6SPC]  119 100.33 0 bottom
R502  10K  [R402-25]  200.66 69.6 180 bottom
R503  10K  [R402-25]  197.74 69.6 0 bottom
R504  330  [R402-25]  216.48 69.52 270 bottom
R505  10K  [R402-25]  197.74 68.33 0 bottom
R506  10K  [R402-25]  203.58 67.69 180 bottom
R507  330  [R402-25]  216.48 67.49 270 bottom
R508  NP  [R402-25]  197.74 67.06 180 bottom
R509  NP  [R402-25]  203.58 66.42 0 bottom
R510  330  [R402-25]  216.48 65.46 270 bottom
R511  0  [R201-6P6SPC]  129.67 91.06 270 bottom
R512  10K  [R402-25]  203.58 65.02 180 bottom
R513  0.01  [R0508]  150.62 94.49 180 bottom
R514  0.01  [R0508]  145.8 94.49 180 bottom
R515  0  [R201-6P6SPC]  68.33 94.36 90 bottom
R516  10K  [R402-25]  203.58 63.75 180 bottom
R517  330  [R402-25]  216.48 63.42 270 bottom
R518  10K  [R402-25]  9.53 92.2 0 bottom
R519  0  [R402-25]  202.69 56.39 270 bottom
R520  0  [R201-6P6SPC]  98.3 91.69 90 bottom
R521  NP  [R402-25]  9.53 91.06 180 bottom
R522  10K  [R402-25]  9.53 89.92 0 bottom
R523  NP  [R402-25]  9.53 88.77 180 bottom
R524  0  [R201-6P6SPC]  70.87 91.19 270 bottom
R525  0  [R201-6P6SPC]  88.39 74.68 90 bottom
R526  0  [R201-6P6SPC]  69.85 91.19 270 bottom
R527  0  [R201-6P6SPC]  85.72 74.68 90 bottom
R528  10K  [R402-25]  67.94 86.49 180 bottom
R529  0  [R201-6P6SPC]  75.95 91.19 270 bottom
R530  0  [R201-6P6SPC]  73.79 91.19 270 bottom
R531  0  [R201-6P6SPC]  72.77 91.19 270 bottom
R532  0  [R201-6P6SPC]  71.75 91.19 270 bottom
R533  0.02  [R603-35X45]  171.83 81.79 90 top
R534  0  [R402-25]  191.77 51.05 270 bottom
R535  NP  [R402-25]  69.72 83.19 180 bottom
R536  0  [R402-25]  69.72 81.15 180 bottom
R537  0.02  [R603-35X45]  173.48 59.94 270 top
R538  10K  [R201-6P6SPC]  148.21 79.88 90 bottom
R539  0  [R402-25]  69.72 82.17 180 bottom
R540  NP  [R402-25]  69.72 80.14 180 bottom
R541  1.5K  [R402-25]  114.3 79.25 90 bottom
R542  0  [R402-25]  69.72 79.12 180 bottom
R543  0  [R402-25]  69.72 78.11 180 bottom
R544  NP  [R201-6P6SPC]  167.39 75.69 270 top
R545  0  [R201-6P6SPC]  166.5 75.69 90 top
R546  2K  [R402-25]  168.4 75.56 90 bottom
R547  1.74K  [R402-25]  170.05 75.06 180 bottom
R548  0.02  [R603-35X45]  180.72 77.6 0 top
R549  0.02  [R603-35X45]  152.53 58.67 180 top
R550  10K  [R402-25]  122.43 40.64 0 bottom
R551  47K  [R402-25]  122.43 42.42 0 bottom
R552  23.2K  [R402-25]  121.41 43.56 180 bottom
R553  22  [R201-6P6SPC]  122.56 62.48 180 bottom
R554  0  [R201-6P6SPC]  109.35 68.33 180 bottom
R555  22  [R201-6P6SPC]  124.84 60.58 180 top
R556  0  [R201-6P6SPC]  109.35 67.31 180 bottom
R557  22  [R201-6P6SPC]  118.24 64.9 180 bottom
R558  0  [R201-6P6SPC]  109.35 67.82 180 top
R559  22  [R201-6P6SPC]  113.41 68.2 180 top
R560  22  [R201-6P6SPC]  118.24 63.63 180 bottom
R561  22  [R201-6P6SPC]  118.24 65.79 180 bottom
R562  22  [R201-6P6SPC]  118.24 62.48 180 bottom
R563  22  [R201-6P6SPC]  122.56 64.52 180 bottom
R564  22  [R201-6P6SPC]  122.56 64.9 180 top
R565  22  [R201-6P6SPC]  118.24 62.87 180 top
R566  22  [R201-6P6SPC]  122.56 63.37 180 bottom
R567  22  [R201-6P6SPC]  118.24 61.59 180 bottom
R568  22  [R201-6P6SPC]  124.84 59.69 180 top
R569  10K  [R402-25]  12.7 23.5 0 top
R570  22  [R201-6P6SPC]  122.56 62.87 180 top
R571  0  [R201-6P6SPC]  115.7 70.36 180 top
R572  10K  [R402-25]  11.18 26.67 180 top
R573  NP  [R201-6P6SPC]  74.93 58.55 0 top
R574  0  [R201-6P6SPC]  118.24 60.71 180 bottom
R575  0.02  [R603-35X45]  177.67 58.67 0 top
R576  NP  [R201-6P6SPC]  74.93 57.66 0 top
R577  22  [R201-6P6SPC]  118.24 64.01 180 top
R578  0  [R201-6P6SPC]  124.84 56.52 180 bottom
R579  0  [R402-25]  15.37 59.18 90 bottom
R580  0  [R201-6P6SPC]  118.24 61.09 180 top
R581  22  [R402-25]  50.42 57.15 0 bottom
R582  0  [R201-6P6SPC]  124.84 57.53 180 bottom
R583  0  [R201-6P6SPC]  124.84 60.2 180 bottom
R584  22  [R402-25]  50.42 56.13 0 bottom
R585  10K  [R402-25]  21.08 57.28 90 bottom
R586  0  [R201-6P6SPC]  124.84 55.63 0 bottom
R587  10K  [R402-25]  8.51 56.64 270 bottom
R588  10K  [R402-25]  7.49 56.64 270 bottom
R589  10K  [R402-25]  6.48 56.64 270 bottom
R590  10K  [R402-25]  5.46 56.64 270 bottom
R591  10K  [R402-25]  4.45 56.64 270 bottom
R592  NP  [R402-25]  19.56 56.26 90 bottom
R593  22  [R402-25]  124.84 53.59 180 bottom
R594  0  [R402-25]  198.12 55.5 270 bottom
R595  NP  [R402-25]  196.85 55.5 270 bottom
R596  0  [R201-6P6SPC]  124.84 54.61 0 bottom
R597  10K  [R201-6P6SPC]  19.43 18.29 90 bottom
R598  22  [R402-25]  124.84 52.58 180 bottom
R599  22  [R402-25]  124.84 51.56 180 bottom
R600  10K  [R402-25]  203.58 51.18 270 bottom
R601  10K  [R402-25]  194.31 51.05 270 bottom
R602  NP  [R402-25]  193.04 51.05 270 bottom
R603  0  [R201-6P6SPC]  117.6 45.21 180 bottom
R604  20K  [R402-25]  180.72 49.66 90 bottom
R605  20K  [R402-25]  178.18 49.66 90 bottom
R606  2K  [R402-25]  175.9 49.66 90 bottom
R607  0  [R201-6P6SPC]  112.39 45.72 180 bottom
R608  10K  [R402-25]  207.65 49.15 0 bottom
R609  10K  [R402-25]  198.37 49.02 0 bottom
R610  2K  [R402-25]  166.75 48.26 0 bottom
R611  22  [R402-25]  121.16 45.85 180 bottom
R612  NP  [R402-25]  166.75 47.12 0 bottom
R613  NP  [R201-6P6SPC]  112.52 43.56 0 bottom
R614  NP  [R402-25]  166.75 45.97 0 bottom
R615  0  [R201-6P6SPC]  201.29 45.59 270 bottom
R616  0  [R402-25]  200.03 45.59 270 bottom
R617  NP  [R402-25]  166.75 44.83 0 bottom
R618  2.2K  [R402-25]  112.14 41.78 270 bottom
R619  20K  [R402-25]  4.32 44.32 90 bottom
R620  20K  [R402-25]  8.38 43.94 90 bottom
R621  20K  [R402-25]  7.37 43.94 90 bottom
R622  20K  [R402-25]  6.35 43.94 90 bottom
R623  20K  [R402-25]  5.33 43.94 90 bottom
R624  0  [R201-6P6SPC]  110.36 47.62 180 bottom
R625  10K  [R201-6P6SPC]  208.03 43.05 180 bottom
R626  2.2K  [R402-25]  112.65 39.62 90 bottom
R628  0  [R402-25]  166.5 41.66 0 bottom
R630  0  [R402-25]  110.62 41.78 90 bottom
R632  2.2K  [R402-25]  166.5 40.51 0 bottom
R633  330  [R402-25]  163.96 40.51 0 bottom
R634  NP  [R402-25]  8.51 40.39 0 bottom
R635  2.2K  [R402-25]  210.31 40.26 90 bottom
R636  2.2K  [R402-25]  209.17 40.26 90 bottom
R637  4.7K  [R402-25]  153.03 40.89 90 bottom
R638  4.7K  [R402-25]  154.05 40.89 90 bottom
R639  2K  [R402-25]  17.02 39.5 180 bottom
R640  0  [R402-25]  155.07 40.89 90 bottom
R641  NP  [R402-25]  111 39.62 90 bottom
R642  0.01  [R0508]  132.59 40.64 270 bottom
R643  10K  [R402-25]  115.7 39.5 180 bottom
R644  4.7k  [R402-25]  25.91 44.32 270 bottom
R645  NP  [R402-25]  166.5 38.23 0 bottom
R646  2K  [R402-25]  17.02 38.23 180 bottom
R647  10K  [R402-25]  205.61 84.96 180 bottom
R648  2.2K  [R402-25]  210.57 36.96 270 bottom
R649  2.2K  [R402-25]  209.3 36.96 270 bottom
R650  4.7k  [R402-25]  17.53 35.81 270 bottom
R651  4.7K  [R402-25]  157.48 40.89 90 bottom
R652  NP  [R402-25]  156.34 40.89 270 bottom
R653  0  [R1206-40X70]  136.4 42.04 0 bottom
R654  1K  [R402-25]  177.16 33.66 270 bottom
R655  0  [R201-6P6SPC]  172.59 21.08 90 bottom
R656  0  [R201-6P6SPC]  171.7 21.08 90 bottom
R657  0  [R201-6P6SPC]  170.81 21.08 90 bottom
R658  4.7K  [R402-25]  158.5 35.18 90 bottom
R659  4.7K  [R402-25]  157.48 34.54 270 bottom
R662  4.99K  [R603-35X45]  3.17 33.53 180 bottom
R663  4.7K  [R402-25]  156.46 35.18 270 bottom
R664  0  [R402-25]  156.34 38.23 90 bottom
R665  100  [R402-25]  155.45 35.18 90 bottom
R666  NP  [R402-25]  178.94 33.15 0 bottom
R667  10K  [R402-25]  138.68 37.72 90 bottom
R668  NP  [R402-25]  26.16 36.7 90 bottom
R669  NP  [R402-25]  24.89 36.7 90 bottom
R670  NP  [R402-25]  208.28 34.42 0 bottom
R671  0.01  [R0508]  145.8 31.11 270 bottom
R672  4.7K  [R402-25]  137.92 28.32 0 top
R673  NP  [R402-25]  197.23 32.64 180 bottom
R674  18.2  [R402-25]  137.92 27.18 0 bottom
R675  36  [R402-25]  97.79 26.67 0 bottom
R676  18.2  [R402-25]  137.92 26.16 0 bottom
R677  NP  [R402-25]  40.51 25.53 90 bottom
R678  NP  [R402-25]  30.1 60.58 270 bottom
R679  NP  [R402-25]  29.08 60.58 90 bottom
R680  NP  [R402-25]  28.07 60.58 270 bottom
R681  0  [R402-25]  27.05 60.58 90 bottom
R682  NP  [R402-25]  26.04 60.58 270 bottom
R683  0  [R402-25]  25.02 60.58 90 bottom
R684  36  [R402-25]  97.79 25.65 0 bottom
R685  4.7K  [R402-25]  97.79 26.8 0 top
R686  36  [R402-25]  97.79 25.78 0 top
R687  10K  [R402-25]  217.04 23.75 0 bottom
R688  16K  [R402-25]  152.15 22.48 270 top
R689  10K  [R402-25]  202.31 32.64 0 bottom
R690  240  [R402-25]  82.3 22.83 0 bottom
R691  240  [R402-25]  69.6 22.83 0 bottom
R692  20K  [R402-25]  151.13 22.48 90 top
R693  240  [R402-25]  94.87 21.97 0 bottom
R694  240  [R402-25]  122.17 21.72 270 bottom
R695  240  [R402-25]  107.82 21.72 270 bottom
R696  100  [R402-25]  173.99 21.08 270 bottom
R697  20K  [R402-25]  193.8 20.45 270 bottom
R698  0  [R402-25]  106.68 14.22 180 bottom
R699  NP  [R402-25]  106.68 13.21 180 bottom
R700  20K  [R402-25]  184.28 15.75 180 bottom
R701  20K  [R402-25]  173.48 15.37 180 bottom
R702  10K  [R201-6P6SPC]  27.69 48.26 90 bottom
R703  0.01  [R0508]  143.89 14.22 0 bottom
R704  240  [R402-25]  120.02 23.5 90 bottom
R705  240  [R402-25]  134.37 23.5 90 bottom
R706  2K  [R402-25]  169.04 79.12 270 bottom
R707  10K  [R402-25]  156.84 60.2 90 bottom
R708  10K  [R402-25]  158.75 60.2 90 bottom
R709  1.5K  [R402-25]  22.1 30.35 270 top
R710  2K  [R402-25]  158.12 72.77 180 bottom
R711  10K  [R402-25]  148.08 103.12 270 bottom
R712  10K  [R201-6P6SPC]  141.99 60.83 0 bottom
R713  330  [R402-25]  210.06 171.58 90 bottom
R714  10K  [R402-25]  47.24 120.27 180 bottom
R716  9.53K  [R402-25]  54.36 114.3 90 top
R717  1M  [R402-25]  53.85 128.02 0 top
R719  4.7K  [R402-25]  47.24 119.25 0 bottom
R722  4.7K  [R402-25]  55.88 124.08 0 bottom
R724  4.7K  [R402-25]  44.7 120.27 180 bottom
R725  NP-4.7K  [R402-25]  53.09 116.97 270 bottom
R726  NP-4.7K  [R402-25]  48.26 127.76 0 bottom
R727  NP-4.7K  [R402-25]  48.26 131.06 0 bottom
R728  20K  [R402-25]  179.32 105.16 180 bottom
R729  10K  [R201-6P6SPC]  127.64 106.81 90 bottom
R730  10K  [R201-6P6SPC]  124.71 106.81 90 bottom
R731  4.7K  [R402-25]  52.07 116.97 270 bottom
R732  4.7K  [R402-25]  55.88 125.6 0 bottom
R733  2.2K  [R402-25]  121.92 73.28 180 top
R734  2.2K  [R402-25]  121.92 72.26 180 top
R735  10  [R201-6P6SPC]  155.45 54.1 180 top
R736  10  [R201-6P6SPC]  155.45 52.58 180 top
R737  10K  [R201-6P6SPC]  166.24 53.47 180 top
R738  4.7k  [R402-25]  35.69 51.31 180 top
R739  4.7k  [R402-25]  34.04 58.55 270 top
R740  4.7k  [R402-25]  35.05 58.55 270 top
R742  274K  [R402-25]  199.52 131.57 90 bottom
R743  100K  [R402-25]  198.37 132.59 270 bottom
R744  100K  [R402-25]  199.64 127 270 bottom
R745  10K  [R201-6P6SPC]  210.44 92.71 180 bottom
R746  10K  [R201-6P6SPC]  210.44 91.44 180 bottom
R747  10K  [R201-6P6SPC]  210.44 90.17 180 bottom
R748  10K  [R201-6P6SPC]  210.44 88.9 180 bottom
R749  1K  [R201-6P6SPC]  218.06 92.71 0 bottom
R750  1K  [R201-6P6SPC]  218.06 91.44 0 bottom
R751  1K  [R201-6P6SPC]  218.06 90.17 0 bottom
R752  1K  [R201-6P6SPC]  218.06 88.9 0 bottom
R753  100  [R402-25]  190.75 65.41 90 bottom
R754  10K  [R402-25]  190.12 63.5 180 bottom
R755  10K  [R402-25]  187.2 63.25 270 bottom
R756  20K  [R402-25]  200.91 127 90 bottom
RJ1  4.7K  [JMP402-25]  86.23 167.89 180 top
RJ2  0.B  [JMP402-25]  78.99 153.92 180 top
RJ3  22  [JMP402-25]  153.92 148.46 180 top
RJ4  22  [JMP402-25]  155.96 147.07 270 top
RJ5  22  [JMP402-25]  153.92 147.19 180 top
RJ6  4.7K  [JMP402-25]  30.99 97.92 180 top
RJ7  0.A  [JMP402-25]  133.35 96.77 90 top
RJ8  0.A  [JMP402-25]  134.87 96.77 90 top
RJ9  0.A  [JMP402-25]  136.4 96.77 90 top
RJ10  0.A  [JMP402-25]  137.92 96.77 90 top
RJ12  0  [JMP402-25]  121.79 177.67 180 bottom
RJ13  0  [JMP402-25]  100.84 177.67 180 bottom
RJ14  4.7K  [JMP402-25]  158.5 146.81 180 bottom
RJ15  0.A  [JMP402-25]  36.07 117.98 0 bottom
RJ16  0.A  [JMP402-25]  58.67 117.6 0 top
RJ17  0.A  [JMP402-25]  209.04 123.95 180 top
RN1  R-PACK4-36  [RPAK8-10X25-28V]  138.3 24.26 270 top
RN2  R-PACK4-36  [RPAK8-10X25-28V]  98.04 23.62 270 top
RN3  R-PACK4-36  [RPAK8-10X25-28V]  138.3 20.83 270 top
RN4  R-PACK4-36  [RPAK8-10X25-28V]  98.04 20.19 270 top
RN5  R-PACK4-36  [RPAK8-10X25-28V]  138.3 17.4 270 top
RN6  R-PACK4-36  [RPAK8-10X25-28V]  98.04 16.76 270 top
RN7  RPACK4-22  [RPAK8-10X25-28V]  61.85 148.08 0 bottom
RN8  RPACK4-22  [RPAK8-10X25-28V]  59.18 148.08 0 bottom
RN9  RPACK4-22  [RPAK8-10X25-28V]  56.52 148.08 0 bottom
RN10  R-PACK4-36  [RPAK8-10X25-28V]  138.3 24.26 90 bottom
RN11  R-PACK4-36  [RPAK8-10X25-28V]  98.04 23.62 90 bottom
RN12  R-PACK4-36  [RPAK8-10X25-28V]  138.3 20.83 90 bottom
RN13  R-PACK4-36  [RPAK8-10X25-28V]  98.04 20.19 90 bottom
RN14  R-PACK4-36  [RPAK8-10X25-28V]  138.3 17.4 90 bottom
RN15  R-PACK4-36  [RPAK8-10X25-28V]  98.04 16.76 90 bottom
RU1  74CBTLV1G125CRG4  [DCK-5]  55.12 160.53 90 top
RU2  SN74CBTLV3257PW  [TSSOP16-14X70]  166.37 155.45 180 top
RU3  74CBTLV1G125CRG4  [DCK-5]  117.09 147.7 270 top
RU4  SN74CBTLV3257PW  [TSSOP16-14X70]  123.7 115.44 0 top
RU5  SN74CBTLV16212GR  [DGG56-12X80]  137.67 114.81 0 top
RU6  74CBTLV1G125CRG4  [DCK-5]  123.7 101.6 0 top
RU7  SN74CBTLV16212GR  [DGG56-12X80]  92.58 97.66 0 top
RU8  SN74CBT16214DGGR  [DGG56-12X80]  109.73 97.66 0 top
RU9  SN74CBTLV3245DBQ  [DBQ20-14X70]  137.41 82.17 0 top
RU10  SN74CBTLV3257PW  [TSSOP16-14X70]  200.79 38.61 270 top
RU11  74CBTLV1G125CRG4  [DCK-5]  205.87 85.98 0 top
RU12  74CBTLV1G125CRG4  [DCK-5]  146.3 149.86 270 bottom
RU13  SN74CBTLV16212GR  [DGG56-12X80]  137.67 114.81 180 bottom
RU14  SN74CBTLV3257PW  [TSSOP16-14X70]  57.66 111.25 180 bottom
RU15  SN74CBT16214DGGR  [DGG56-12X80]  109.73 97.66 180 bottom
RU16  SN74CBTLV16212GR  [DGG56-12X80]  92.58 97.66 180 bottom
RU17  SN74CBTLV16212GR  [DGG56-12X80]  76.07 97.66 180 bottom
RU18  SN74CBTLV16212GR  [DGG56-12X80]  136.4 97.41 180 bottom
RU19  SN74CBTLV3257PW  [TSSOP16-14X70]  158.88 92.71 270 bottom
RU20  SN74CBTLV3245DBQ  [DBQ20-14X70]  137.41 82.17 180 bottom
RU21  SN74CBTLV3257PW  [TSSOP16-14X70]  14.22 16.38 270 bottom
RU22  SN74CBTLV3257PW  [TSSOP16-14X70]  155.45 52.83 270 bottom
RU23  SN74CBTLV3257PW  [TSSOP16-14X70]  155.45 45.97 270 bottom
RU24  74CBTLV1G125CRG4  [DCK-5]  162.56 51.05 180 top
RU25  74CBTLV1G125CRG4  [DCK-5]  165.23 51.05 180 top
SW1  SW DIP-2  [SW2-30X50-TDA]  40.39 175.01 270 top
SW2  PB_SW  [SW4-7914G]  198.25 174.37 0 top
SW3  TDA08H0SB1R  [SW8-30X50]  122.43 129.54 0 top
SW4  TDA08H0SB1R  [SW8-30X50]  134.62 129.54 0 top
SW5  PB_SW  [SW4-7914G]  215.65 131.44 180 top
SW6  TDA10H0SK1  [SW10-30X50]  214.25 78.87 90 top
SW7  PB_SW  [SW4-7914G]  172.85 96.9 180 top
SW8  PB_SW  [SW4-7914G]  206.12 53.09 0 top
SW9  PB_SW  [SW4-7914G]  196.85 52.96 0 top
SW10  TDA04H0SB1R  [SW4-30X50-TDA]  214.25 90.81 90 top
TP1  SMT-TP  [TP1-70X135]  214.25 167.13 0 top
TP2  TP  [TP1-6040]  190.12 78.11 0 top
TP2MA1  TP_VIA_MEM0  [TP1-18RD8]  113.54 25.55 180 top
TP2MA2  TP_VIA_MEM0  [TP1-18RD8]  113.89 25.07 180 top
TP2MA3  TP_VIA_MEM0  [TP1-18RD8]  114.71 25.04 180 top
TP2MA4  TP_VIA_MEM0  [TP1-18RD8]  114.55 24.41 180 top
TP2MA5  TP_VIA_MEM0  [TP1-18RD8]  113.16 24.21 180 top
TP2MA6  TP_VIA_MEM0  [TP1-18RD8]  113.79 24 180 top
TP2MA7  TP_VIA_MEM0  [TP1-18RD8]  114.63 23.44 180 top
TP2MA8  TP_VIA_MEM0  [TP1-18RD8]  113.21 23.37 180 top
TP2MA9  TP_VIA_MEM0  [TP1-18RD8]  113.86 22.86 180 top
TP2MA10  TP_VIA_MEM0  [TP1-18RD8]  113.28 22.48 180 top
TP2MA11  TP_VIA_MEM0  [TP1-18RD8]  114.68 22.23 180 top
TP2MA12  TP_VIA_MEM0  [TP1-18RD8]  114.05 21.84 0 top
TP2MA13  TP_VIA_MEM0  [TP1-18RD8]  113.21 21.62 180 top
TP2MA14  TP_VIA_MEM0  [TP1-18RD8]  114.55 21.16 180 top
TP2MA15  TP_VIA_MEM0  [TP1-18RD8]  113.54 20.83 180 top
TP2MA16  TP_VIA_MEM0  [TP1-18RD8]  113.92 20.32 180 top
TP2MA17  TP_VIA_MEM0  [TP1-18RD8]  114.55 20.19 180 top
TP2MA18  TP_VIA_MEM0  [TP1-18RD8]  113.16 19.79 180 top
TP2MA19  TP_VIA_MEM0  [TP1-18RD8]  114.43 19.25 180 top
TP2MA20  TP_VIA_MEM0  [TP1-18RD8]  113.82 19.05 180 top
TP2MA21  TP_VIA_MEM0  [TP1-18RD8]  113.33 18.69 180 top
TP2MA22  TP_VIA_MEM0  [TP1-18RD8]  114.22 18.16 180 top
TP2MA23  TP_VIA_MEM0  [TP1-18RD8]  115.11 17.88 180 top
TP2MA24  TP_VIA_MEM0  [TP1-18RD8]  113.64 17.86 180 top
TP2MA25  TP_VIA_MEM0  [TP1-18RD8]  114.43 17.02 180 top
TP2MA26  TP_VIA_MEM0  [TP1-18RD8]  115.06 17.02 180 top
TP2MA27  TP_VIA_MEM0  [TP1-18RD8]  112.78 16.76 180 top
TP2MB1  TP_VIA_MEM1  [TP1-18RD8]  127.89 25.55 180 top
TP2MB2  TP_VIA_MEM1  [TP1-18RD8]  128.24 25.07 180 top
TP2MB3  TP_VIA_MEM1  [TP1-18RD8]  129.06 25.04 180 top
TP2MB4  TP_VIA_MEM1  [TP1-18RD8]  128.91 24.41 180 top
TP2MB5  TP_VIA_MEM1  [TP1-18RD8]  127.51 24.21 180 top
TP2MB6  TP_VIA_MEM1  [TP1-18RD8]  128.14 24 180 top
TP2MB7  TP_VIA_MEM1  [TP1-18RD8]  128.98 23.47 180 top
TP2MB8  TP_VIA_MEM1  [TP1-18RD8]  127.56 23.37 180 top
TP2MB9  TP_VIA_MEM1  [TP1-18RD8]  128.21 22.86 180 top
TP2MB10  TP_VIA_MEM1  [TP1-18RD8]  127.64 22.48 180 top
TP2MB11  TP_VIA_MEM1  [TP1-18RD8]  129.03 22.23 180 top
TP2MB12  TP_VIA_MEM1  [TP1-18RD8]  128.4 21.84 0 top
TP2MB13  TP_VIA_MEM1  [TP1-18RD8]  127.56 21.62 180 top
TP2MB14  TP_VIA_MEM1  [TP1-18RD8]  128.91 21.16 180 top
TP2MB15  TP_VIA_MEM1  [TP1-18RD8]  127.89 20.83 180 top
TP2MB16  TP_VIA_MEM1  [TP1-18RD8]  128.27 20.32 180 top
TP2MB17  TP_VIA_MEM1  [TP1-18RD8]  128.91 20.19 180 top
TP2MB18  TP_VIA_MEM1  [TP1-18RD8]  127.51 19.79 180 top
TP2MB19  TP_VIA_MEM1  [TP1-18RD8]  128.78 19.25 180 top
TP2MB20  TP_VIA_MEM1  [TP1-18RD8]  128.17 19.05 180 top
TP2MB21  TP_VIA_MEM1  [TP1-18RD8]  127.69 18.69 180 top
TP2MB22  TP_VIA_MEM1  [TP1-18RD8]  128.57 18.16 180 top
TP2MB23  TP_VIA_MEM1  [TP1-18RD8]  129.46 17.88 180 top
TP2MB24  TP_VIA_MEM1  [TP1-18RD8]  127.99 17.86 180 top
TP2MB25  TP_VIA_MEM1  [TP1-18RD8]  128.78 17.02 180 top
TP2MB26  TP_VIA_MEM1  [TP1-18RD8]  129.41 17.02 180 top
TP2MB27  TP_VIA_MEM1  [TP1-18RD8]  127.13 16.76 180 top
TP3  SMT-TP  [TP1-70X135]  24.89 175.51 0 top
TP4  TP  [TP1-18RD8]  71.25 174.75 90 bottom
TP5  TP  [TP1-18RD8]  14.48 171.45 270 top
TP6  TP  [TP1-18RD8]  34.54 158.88 0 top
TP7  TP  [TP-30RD13]  105.41 153.67 0 top
TP8  TP  [TP1-6040]  44.32 149.73 90 top
TP9  TP  [TP1-18RD8]  164.59 135.38 0 top
TP10  NP  [TP20]  17.78 144.4 0 top
TP11  TP  [TP-20RD10]  21.21 145.92 90 top
TP12  TP  [TP1-6040]  23.11 160.91 0 top
TP13  TP  [TP-30RD13]  111.76 133.99 0 top
TP14  TP  [TP-30RD13]  18.54 131.57 0 top
TP15  NP  [TP20]  214.5 138.43 0 top
TP16  TP  [TP-30RD13]  25.15 130.81 0 top
TP17  TP  [TP-30RD13]  34.8 132.08 0 top
TP18  TP  [TP-30RD13]  34.8 130.05 0 top
TP19  TP  [TP-30RD13]  22.99 113.03 0 top
TP20  TP  [TP1-18RD8]  114.68 121.67 0 top
TP21  TP  [TP1-18RD8]  114.68 120.52 0 top
TP22  TP  [TP-30RD13]  28.32 112.52 0 top
TP23  TP  [TP1-18RD8]  115.39 117.93 0 top
TP24  TP  [TP1-18RD8]  120.19 117.93 0 top
TP25  TP  [TP1-18RD8]  119.39 117.17 0 top
TP26  TP  [TP-30RD13]  32 112.65 0 top
TP27  TP  [TP1-18RD8]  104.52 103.76 0 top
TP28  TP  [TP1-18RD8]  119.63 111.51 0 top
TP29  TP  [TP1-18RD8]  119.39 108.03 0 top
TP30  TP  [TP1-18RD8]  120.19 107.52 0 top
TP31  6p6spc  [6P6SPC]  17.55 106.55 270 top
TP32  6p6spc  [6P6SPC]  17.65 105.03 90 top
TP33  6p6spc  [6P6SPC]  19.63 103.56 270 top
TP34  6p6spc  [6P6SPC]  19.63 101.8 90 top
TP35  6p6spc  [6P6SPC]  19.63 99.49 270 top
TP36  6p6spc  [6P6SPC]  19.63 97.87 90 top
TP37  6p6spc  [6P6SPC]  17.6 96.44 270 top
TP38  6p6spc  [6P6SPC]  17.6 94.82 90 top
TP39  TP  [TP1-18RD8]  3.05 91.31 0 top
TP40  TP  [TP1-18RD8]  118.49 88.42 0 top
TP41  TP  [TP1-18RD8]  127.64 88.42 0 top
TP42  TP  [TP1-18RD8]  117.47 85.22 0 top
TP43  TP  [TP1-18RD8]  128.52 85.22 0 top
TP44  TP  [TP1-18RD8]  118.49 85.22 0 top
TP45  TP  [TP1-18RD8]  127.64 85.22 0 top
TP46  TP  [TP1-18RD8]  118.49 83.62 0 top
TP47  TP  [TP1-18RD8]  127.64 83.62 0 top
TP48  TP  [TP1-18RD8]  117.47 83.57 0 top
TP49  TP  [TP1-18RD8]  128.52 82.04 0 top
TP50  TP  [TP1-18RD8]  118.49 82.02 0 top
TP51  TP  [TP1-18RD8]  127.64 82.02 0 top
TP52  TP  [TP1-18RD8]  117.47 81.92 0 top
TP53  TP  [TP1-18RD8]  128.27 81.23 0 top
TP54  NP  [TP-30RD13]  170.31 79.63 90 top
TP55  TP  [TP1-18RD8]  97.92 75.82 0 top
TP56  TP  [TP1-18RD8]  115.32 69.6 0 top
TP57  TP  [TP1-18RD8]  108.97 64.39 0 top
TP58  NP  [TP-30RD13]  158.24 74.8 90 top
TP59  NP  [TP-30RD13]  170.94 65.28 90 top
TP60  NP  [TP-30RD13]  169.29 65.28 90 top
TP61  NP  [TP-30RD13]  158.62 64.39 90 top
TP62  NP  [TP-30RD13]  158.62 62.87 90 top
TP63  TP  [TP-20RD10]  1.65 62.1 270 top
TP64  TP  [TP-20RD10]  13.34 61.59 270 top
TP65  TP  [TP-20RD10]  117.86 55.5 0 top
TP66  TP  [TP20]  51.44 47.88 90 top
TP67  TP  [TP20]  44.7 54.48 90 bottom
TP68  TP  [TP20]  43.69 54.48 90 bottom
TP69  TP  [TP-30RD13]  43.31 42.42 0 top
TP70  TP  [TP-30RD13]  204.34 47.75 0 top
TP71  TP  [TP-30RD13]  200.03 47.75 0 top
TP72  TP  [TP-30RD13]  43.31 40.89 0 top
TP73  TP  [TP-30RD13]  43.31 44.32 0 top
TP74  TP  [TP-30RD13]  124.46 48.51 0 top
TP75  TP  [TP-20RD10]  117.86 52.7 0 top
TP76  TP  [TP-20RD10]  1.65 40.26 270 top
TP77  TP  [TP-20RD10]  13.84 40.01 270 top
TP78  TP  [TP-20RD10]  1.65 39.24 270 top
TP79  TP  [TP-20RD10]  13.34 39.24 270 top
TP80  TP  [TP-20RD10]  13.84 38.48 270 top
TP81  TP  [TP-20RD10]  1.65 38.23 270 top
